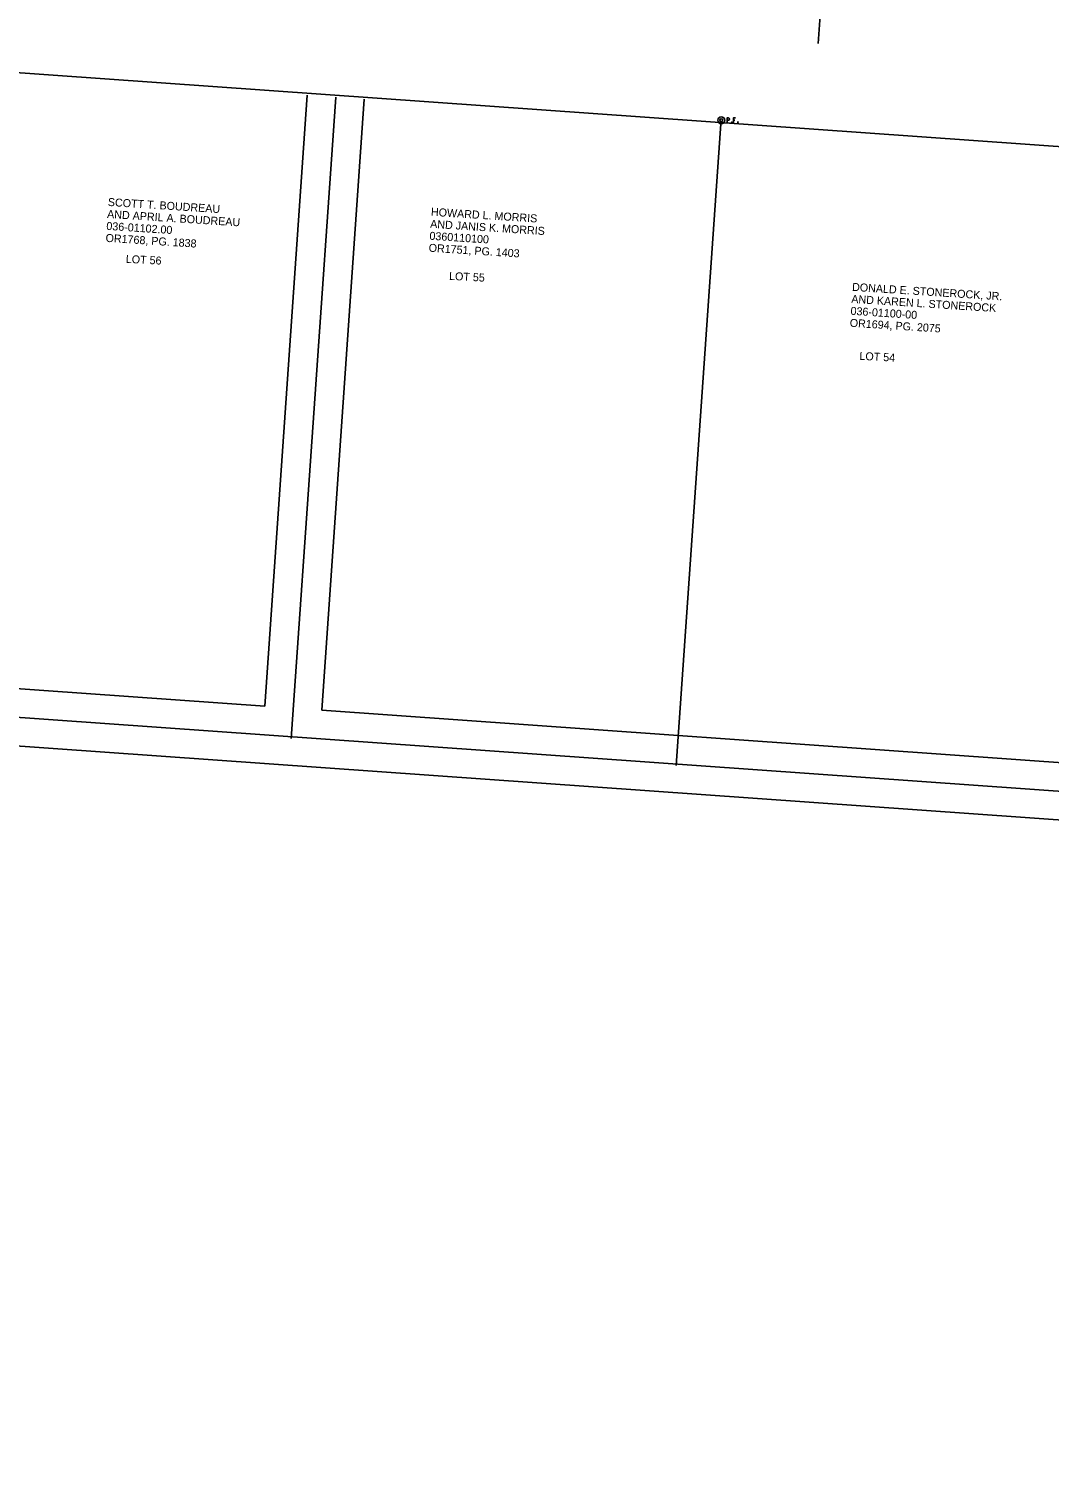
# Model space of a CAD drawing. Extents: x 1898254 to 1901377, y 701554 to 704886.
# Drawn here: x 1898611 to 1898968, y 702797 to 703301 of the extents above; entities that cross this region are included whole.
import ezdxf

# ---------------------------------------------------------------- set-up
doc = ezdxf.new("R2010")
doc.units = 0
for name, color, linetype in [('DV_X_Property_Line', 7, 'Continuous'), ('DV_X_Text', 7, 'Continuous'), ('RW_X_Esmt_General', 7, 'Continuous'), ('RW_X_Fee_RW', 7, 'Continuous'), ('SC_Scratch2', 7, 'Continuous'), ('SV_X_Mon_Cells_Found', 7, 'Continuous')]:
    doc.layers.add(name, color=color, linetype=linetype)

msp = doc.modelspace()

# ---------------------------------------------------------------- linework, layer by layer
at = {"layer": 'DV_X_Property_Line'}
for p, q in [((1898887.4, 703295.86), (1898904.77, 703545.25)), ((1898703.01, 703052.67), (1898718.65, 703277.12)), ((1898837.69, 703043.29), (1898853.32, 703267.74)), ((1899469, 702998.85), (1898413.79, 703073.89))]:
    msp.add_line(p, q, dxfattribs=at)
at = {"layer": 'RW_X_Esmt_General'}
for p, q in [((1898693.78, 703064.01), (1898708.67, 703277.82)), ((1898713.73, 703062.59), (1898728.62, 703276.43)), ((1898693.78, 703064.01), (1898579.07, 703072.16)), ((1899458.32, 702989.59), (1898413.09, 703063.91)), ((1898988.04, 703043.08), (1898713.73, 703062.59))]:
    msp.add_line(p, q, dxfattribs=at)
at = {"layer": 'RW_X_Fee_RW'}
msp.add_line((1899763.77, 703203.46), (1898449.4, 703296.93), dxfattribs=at)
at = {"layer": 'SC_Scratch2'}
msp.add_circle((1899815.76, 703229.84), 1561.35, dxfattribs=at)
at = {"layer": 'SV_X_Mon_Cells_Found'}
for points in [[(1898855.47, 703268.22), (1898855.47, 703269.82), (1898856, 703269.82), (1898856.06, 703269.8), (1898856.14, 703269.78), (1898856.17, 703269.75), (1898856.2, 703269.73), (1898856.25, 703269.67), (1898856.28, 703269.6), (1898856.3, 703269.5), (1898856.3, 703269.35), (1898856.29, 703269.3), (1898856.27, 703269.22), (1898856.22, 703269.14), (1898856.18, 703269.1), (1898856.15, 703269.07), (1898856.09, 703269.05), (1898856, 703269.04), (1898855.47, 703269.04)], [(1898857.12, 703268.43), (1898857.17, 703268.43), (1898857.2, 703268.41), (1898857.24, 703268.36), (1898857.24, 703268.29), (1898857.2, 703268.24), (1898857.17, 703268.22), (1898857.12, 703268.22), (1898857.08, 703268.24), (1898857.05, 703268.29), (1898857.05, 703268.36), (1898857.08, 703268.41), (1898857.12, 703268.43)], [(1898858.48, 703269.82), (1898857.72, 703269.82), (1898857.72, 703268.22)], [(1898857.72, 703269.04), (1898858.26, 703269.04)], [(1898859.27, 703268.43), (1898859.32, 703268.43), (1898859.35, 703268.41), (1898859.39, 703268.36), (1898859.39, 703268.29), (1898859.35, 703268.24), (1898859.32, 703268.22), (1898859.27, 703268.22), (1898859.23, 703268.24), (1898859.2, 703268.29), (1898859.2, 703268.36), (1898859.23, 703268.41), (1898859.27, 703268.43)]]:
    msp.add_lwpolyline(points, dxfattribs=at)
for radius in [1.2, 0.495]:
    msp.add_circle((1898853.48, 703269.02), radius, dxfattribs=at)

# ---------------------------------------------------------------- texts
at = {"layer": 'DV_X_Text'}
for s, rotation, p in [('AND APRIL A. BOUDREAU', 356.3351, (1898638.6, 703234.88)), ('SCOTT T. BOUDREAU', 356.3351, (1898638.86, 703239.07)), ('HOWARD L. MORRIS ', 356.3351, (1898751.86, 703235.63)), ('036-01102.00', 356.3351, (1898638.33, 703230.69)), ('AND JANIS K. MORRIS ', 356.3351, (1898751.59, 703231.43)), ('OR1768, PG. 1838', 356.3351, (1898638.06, 703226.5)), ('0360110100', 356.3351, (1898751.33, 703227.24)), ('OR1751, PG. 1403', 356.3351, (1898751.06, 703223.05)), ('LOT 56', 357.0949, (1898645.15, 703219.13)), ('LOT 55', 357.0949, (1898758.21, 703213.18)), ('DONALD E. STONEROCK, JR.', 356.3351, (1898899.15, 703209.36)), ('AND KAREN L. STONEROCK', 356.3351, (1898898.88, 703205.17)), ('036-01100-00', 356.3351, (1898898.61, 703200.98)), ('OR1694, PG. 2075', 356.3351, (1898898.34, 703196.79)), ('LOT 54', 357.0949, (1898901.73, 703185.21))]:
    msp.add_text(s, height=2.8, rotation=rotation, dxfattribs=at).set_placement(p)

doc.saveas('drawing.dxf')
